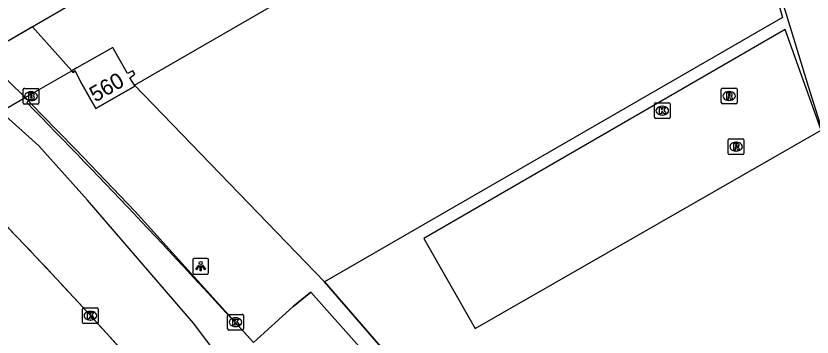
# Model space of a CAD drawing. Extents: x 155018 to 156648, y 383980 to 385733.
# Drawn here: x 155964.6 to 156015.3, y 385032.4 to 385052.9 of the extents above; entities that cross this region are included whole.
import ezdxf

# ---------------------------------------------------------------- set-up
doc = ezdxf.new("R2010")
doc.units = 0
for name, color, linetype in [('IMGEO_Brandkraan', 7, 'Continuous'), ('IMGEO_Dek', 7, 'Continuous'), ('IMGEO_Hek', 7, 'Continuous'), ('IMGEO_Kolk', 7, 'Continuous'), ('IMGEO_Lichtpunt', 7, 'Continuous'), ('IMGEO_OVBaan_gesloten', 7, 'Continuous'), ('IMGEO_Pand', 7, 'Continuous'), ('IMGEO_Pand_nummerreeks', 7, 'Continuous'), ('IMGEO_Pand_overbouw', 7, 'Continuous'), ('IMGEO_Parkeervlak_open', 7, 'Continuous'), ('IMGEO_Rijbaan_lokaal_gesloten', 7, 'Continuous'), ('IMGEO_Rijbaan_lokaal_open', 7, 'Continuous'), ('IMGEO_Rioolput', 7, 'Continuous'), ('IMGEO_Voetpad_gesloten', 7, 'Continuous'), ('IMGEO_Voetpad_open', 7, 'Continuous')]:
    doc.layers.add(name, color=color, linetype=linetype)

msp = doc.modelspace()

# ---------------------------------------------------------------- linework, layer by layer
at = {"layer": 'IMGEO_Brandkraan'}
for p, q in [((155965.097, 385047.34), (155965.097, 385048.192)), ((155965.172, 385048.266), (155966.024, 385048.266)), ((155966.098, 385048.192), (155966.098, 385047.34)), ((155965.585, 385048.046), (155965.61, 385048.046)), ((155966.024, 385047.266), (155965.172, 385047.266)), ((155965.608, 385047.486), (155965.583, 385047.486))]:
    msp.add_line(p, q, dxfattribs=at)
for points in [[(155965.097, 385047.34), (155965.097, 385048.192)], [(155965.172, 385048.266), (155966.024, 385048.266)], [(155966.098, 385048.192), (155966.098, 385047.34)], [(155965.445, 385047.966), (155965.445, 385047.566), (155965.658, 385047.566)], [(155965.676, 385047.966), (155965.445, 385047.966)], [(155965.624, 385047.885), (155965.57, 385047.885), (155965.57, 385047.809)], [(155965.57, 385047.809), (155965.623, 385047.809)], [(155965.632, 385047.733), (155965.57, 385047.733), (155965.57, 385047.652)], [(155965.57, 385047.652), (155965.632, 385047.652)], [(155966.024, 385047.266), (155965.172, 385047.266)]]:
    msp.add_lwpolyline(points, dxfattribs=at)
for centre, radius, start, end in [((155965.174, 385048.19), 0.0765, 91.552, 178.448), ((155965.174, 385048.19), 0.0765, 91.552, 178.448), ((155966.022, 385048.19), 0.0765, 1.552, 88.448), ((155966.022, 385048.19), 0.0765, 1.552, 88.448), ((155965.625, 385047.847), 0.0379, 267.8285, 90.9355), ((155965.633, 385047.692), 0.0404, 269.8759, 90.5077), ((155965.68, 385047.821), 0.145, 59.4692, 91.5367), ((155965.705, 385047.868), 0.0922, 285.5137, 58.1501), ((155965.71, 385047.676), 0.105, 301.3115, 78.989), ((155965.174, 385047.342), 0.0765, 181.552, 268.448), ((155965.174, 385047.342), 0.0765, 181.552, 268.448), ((155965.664, 385047.817), 0.251, 268.6676, 293.5347), ((155966.022, 385047.342), 0.0765, 271.552, 358.448), ((155966.022, 385047.342), 0.0765, 271.552, 358.448)]:
    msp.add_arc(centre, radius, start, end, dxfattribs=at)
for centre, major_axis, ratio, start_param, end_param in [((155965.584, 385047.766), (-0.387, 0.002), 0.722429, 4.712389, 7.853982), ((155965.609, 385047.766), (-0.39, 0.002), 0.717154, 1.570796, 4.712389)]:
    msp.add_ellipse(centre, major_axis=major_axis, ratio=ratio, start_param=start_param, end_param=end_param, dxfattribs=at)
at = {"layer": 'IMGEO_Dek'}
for points in [[(156017.88, 384995.994), (156015.235, 385000), (156010.18, 385006.034), (156009.47, 385006.881), (155984.292, 385035.94), (155972.197, 385048.471), (155972.178, 385048.46), (155972.215, 385048.398), (155969.718, 385046.978), (155968.762, 385048.658), (155968.405, 385049.379), (155968.276, 385049.284), (155968.2, 385049.386), (155965.699, 385052.187), (155964.931, 385051.744), (155962.573, 385050.383)], [(155963.734, 385039.816), (155965.63, 385037.827), (155967.511, 385035.822), (155969.375, 385033.803), (155971.223, 385031.769), (155973.056, 385029.721), (155974.872, 385027.658), (155972.373, 385025.357), (155980.461, 385016.334), (155993.065, 385002.273), (156005.259, 384985.766)]]:
    msp.add_lwpolyline(points, dxfattribs=at)
at = {"layer": 'IMGEO_Hek'}
for points in [[(155965.674, 385052.172), (155975.998, 385058.126)], [(156000, 385016.657), (155983.428, 385035.286)]]:
    msp.add_lwpolyline(points, dxfattribs=at)
at = {"layer": 'IMGEO_Kolk'}
for p, q in [((156005.306, 385046.42), (156005.306, 385047.272)), ((156005.381, 385047.346), (156006.233, 385047.346)), ((156006.307, 385047.272), (156006.307, 385046.42)), ((156005.794, 385047.126), (156005.819, 385047.126)), ((156006.233, 385046.346), (156005.381, 385046.346)), ((156005.817, 385046.566), (156005.792, 385046.566)), ((155968.878, 385033.361), (155968.878, 385034.213)), ((155968.953, 385034.287), (155969.805, 385034.287)), ((155969.366, 385034.067), (155969.391, 385034.067)), ((155969.879, 385034.213), (155969.879, 385033.361)), ((155969.389, 385033.507), (155969.364, 385033.507)), ((155978.121, 385032.95), (155978.121, 385033.802)), ((155978.196, 385033.876), (155979.048, 385033.876)), ((155978.609, 385033.656), (155978.634, 385033.656)), ((155979.122, 385033.802), (155979.122, 385032.95)), ((155969.805, 385033.287), (155968.953, 385033.287)), ((155978.632, 385033.096), (155978.607, 385033.096)), ((155979.048, 385032.876), (155978.196, 385032.876))]:
    msp.add_line(p, q, dxfattribs=at)
for points in [[(156005.306, 385046.42), (156005.306, 385047.272)], [(156005.381, 385047.346), (156006.233, 385047.346)], [(156006.307, 385047.272), (156006.307, 385046.42)], [(156005.627, 385047.046), (156005.75, 385047.046), (156005.75, 385046.895), (156005.88, 385047.046), (156006.044, 385047.046), (156005.898, 385046.895), (156006.051, 385046.646), (156005.899, 385046.646), (156005.814, 385046.81), (156005.75, 385046.743), (156005.75, 385046.646), (156005.627, 385046.646), (156005.627, 385047.046)], [(156006.233, 385046.346), (156005.381, 385046.346)], [(155968.878, 385033.361), (155968.878, 385034.213)], [(155968.953, 385034.287), (155969.805, 385034.287)], [(155969.199, 385033.987), (155969.322, 385033.987), (155969.322, 385033.836), (155969.452, 385033.987), (155969.616, 385033.987), (155969.47, 385033.836), (155969.623, 385033.587), (155969.471, 385033.587), (155969.386, 385033.751), (155969.322, 385033.684), (155969.322, 385033.587), (155969.199, 385033.587), (155969.199, 385033.987)], [(155969.879, 385034.213), (155969.879, 385033.361)], [(155978.121, 385032.95), (155978.121, 385033.802)], [(155978.196, 385033.876), (155979.048, 385033.876)], [(155978.442, 385033.576), (155978.565, 385033.576), (155978.565, 385033.425), (155978.695, 385033.576), (155978.859, 385033.576), (155978.713, 385033.425), (155978.866, 385033.176), (155978.714, 385033.176), (155978.629, 385033.34), (155978.565, 385033.273), (155978.565, 385033.176), (155978.442, 385033.176), (155978.442, 385033.576)], [(155979.122, 385033.802), (155979.122, 385032.95)], [(155969.805, 385033.287), (155968.953, 385033.287)], [(155979.048, 385032.876), (155978.196, 385032.876)]]:
    msp.add_lwpolyline(points, dxfattribs=at)
for centre, start, end in [((156005.383, 385047.27), 91.552, 178.448), ((156005.383, 385047.27), 91.552, 178.448), ((156006.231, 385047.27), 1.552, 88.448), ((156006.231, 385047.27), 1.552, 88.448), ((156005.383, 385046.422), 181.552, 268.448), ((156005.383, 385046.422), 181.552, 268.448), ((156006.231, 385046.422), 271.552, 358.448), ((156006.231, 385046.422), 271.552, 358.448), ((155968.955, 385034.211), 91.552, 178.448), ((155968.955, 385034.211), 91.552, 178.448), ((155969.803, 385034.211), 1.552, 88.448), ((155969.803, 385034.211), 1.552, 88.448), ((155978.198, 385033.8), 91.552, 178.448), ((155978.198, 385033.8), 91.552, 178.448), ((155979.046, 385033.8), 1.552, 88.448), ((155979.046, 385033.8), 1.552, 88.448), ((155968.955, 385033.363), 181.552, 268.448), ((155968.955, 385033.363), 181.552, 268.448), ((155969.803, 385033.363), 271.552, 358.448), ((155969.803, 385033.363), 271.552, 358.448), ((155978.198, 385032.952), 181.552, 268.448), ((155978.198, 385032.952), 181.552, 268.448), ((155979.046, 385032.952), 271.552, 358.448), ((155979.046, 385032.952), 271.552, 358.448)]:
    msp.add_arc(centre, 0.0765, start, end, dxfattribs=at)
for centre, major_axis, ratio, start_param, end_param in [((156005.793, 385046.846), (-0.387, 0.002), 0.722429, 4.712389, 7.853982), ((156005.818, 385046.846), (-0.39, 0.002), 0.717154, 1.570796, 4.712389), ((155969.365, 385033.787), (-0.387, 0.002), 0.722429, 4.712389, 7.853982), ((155969.39, 385033.787), (-0.39, 0.002), 0.717154, 1.570796, 4.712389), ((155978.608, 385033.376), (-0.387, 0.002), 0.722429, 4.712389, 7.853982), ((155978.633, 385033.376), (-0.39, 0.002), 0.717154, 1.570796, 4.712389)]:
    msp.add_ellipse(centre, major_axis=major_axis, ratio=ratio, start_param=start_param, end_param=end_param, dxfattribs=at)
at = {"layer": 'IMGEO_Lichtpunt'}
for p, q in [((155975.904, 385037.344), (155975.904, 385036.537)), ((155975.904, 385037.344), (155975.904, 385036.537)), ((155976.806, 385037.439), (155975.998, 385037.439)), ((155976.806, 385037.439), (155975.998, 385037.439)), ((155976.9, 385036.537), (155976.9, 385037.344)), ((155976.9, 385036.537), (155976.9, 385037.344)), ((155975.998, 385036.443), (155976.806, 385036.443)), ((155975.998, 385036.443), (155976.806, 385036.443))]:
    msp.add_line(p, q, dxfattribs=at)
for points in [[(155976.278, 385037.008), (155976.317, 385036.98), (155976.129, 385036.718), (155976.091, 385036.745), (155976.278, 385037.008)], [(155976.49, 385036.98), (155976.528, 385037.007), (155976.715, 385036.745), (155976.676, 385036.717), (155976.49, 385036.98)], [(155976.38, 385036.96), (155976.427, 385036.96), (155976.427, 385036.638), (155976.38, 385036.638), (155976.38, 385036.96)]]:
    msp.add_lwpolyline(points, dxfattribs=at)
msp.add_circle((155976.403, 385037.142), 0.0994, dxfattribs=at)
for centre, start, end in [((155975.998, 385037.344), 90, 180), ((155975.998, 385037.344), 90, 180), ((155976.806, 385037.344), 0, 90), ((155976.806, 385037.344), 0, 90), ((155975.998, 385036.537), 180, 270), ((155975.998, 385036.537), 180, 270), ((155976.806, 385036.537), 270, 0), ((155976.806, 385036.537), 270, 360)]:
    msp.add_arc(centre, 0.0946, start, end, dxfattribs=at)
at = {"layer": 'IMGEO_OVBaan_gesloten'}
for points in [[(155962.573, 385050.383), (155964.168, 385048.718), (155965.231, 385047.677), (155965.428, 385047.477), (155965.321, 385047.362)], [(155959.29, 385044.258), (155965.231, 385047.677)], [(155979.764, 385032.081), (155972.231, 385040.434), (155968.439, 385044.383), (155966.288, 385046.572), (155965.231, 385047.677)]]:
    msp.add_lwpolyline(points, dxfattribs=at)
for centre, radius, start, end in [((155569.91, 384659.169), 554.115, 42.29797, 44.47224), ((155712.784, 384798.739), 347.986, 41.1354, 43.85049), ((155712.784, 384798.739), 347.986, 41.1354, 43.85049)]:
    msp.add_arc(centre, radius, start, end, dxfattribs=at)
at = {"layer": 'IMGEO_Pand'}
for points in [[(155972.197, 385048.471), (156008.671, 385069.52)], [(156008.671, 385069.52), (156013.469, 385052.769), (155984.292, 385035.94)], [(155972.178, 385048.46), (155971.893, 385048.933), (155972.201, 385049.166), (155972.089, 385049.388), (155971.735, 385049.212), (155970.85, 385050.779), (155970.797, 385050.871), (155968.52, 385049.57), (155968.2, 385049.386)], [(155968.2, 385049.386), (155968.276, 385049.284), (155968.405, 385049.379), (155968.762, 385048.658), (155969.718, 385046.978), (155972.215, 385048.398), (155972.178, 385048.46)], [(155972.197, 385048.471), (155984.292, 385035.94)]]:
    msp.add_lwpolyline(points, dxfattribs=at)
at = {"layer": 'IMGEO_Pand_overbouw'}
msp.add_lwpolyline([(156037.638, 384939.699), (156032.938, 384949.258), (156031.228, 384952.424), (156028.885, 384956.762), (156023.824, 384965.729), (156015.329, 384979.293), (156010.047, 384987.197), (156004.748, 384994.572), (156003.959, 384995.67), (155994.678, 385008.257), (155982.028, 385025.261), (155975.946, 385033.308), (155969.19, 385041.146), (155966.094, 385044.608), (155960.986, 385049.184), (155953.94, 385055.371)], dxfattribs=at)
at = {"layer": 'IMGEO_Parkeervlak_open'}
msp.add_lwpolyline([(156029.136, 384994.099), (156032.711, 384996.172), (156033.064, 384996.374), (156024.751, 385019.02), (156019.719, 385033.828), (156015.201, 385048.103), (156012.694, 385056.311), (156008.803, 385069.59)], dxfattribs=at)
at = {"layer": 'IMGEO_Rijbaan_lokaal_gesloten'}
msp.add_lwpolyline([(156015.926, 385045.612), (156013.645, 385052.003), (155990.628, 385038.7), (155993.886, 385032.966), (156015.926, 385045.612)], dxfattribs=at)
at = {"layer": 'IMGEO_Rijbaan_lokaal_open'}
for points in [[(155968.6, 385053.859), (155962.573, 385050.383)], [(155965.231, 385047.677), (155968.2, 385049.386)], [(155972.178, 385048.46), (155972.197, 385048.471)]]:
    msp.add_lwpolyline(points, dxfattribs=at)
at = {"layer": 'IMGEO_Rioolput'}
for p, q in [((156009.567, 385047.354), (156009.567, 385048.206)), ((156009.642, 385048.28), (156010.494, 385048.28)), ((156010.568, 385048.206), (156010.568, 385047.354)), ((156010.055, 385048.06), (156010.08, 385048.06)), ((156010.494, 385047.28), (156009.642, 385047.28)), ((156010.078, 385047.5), (156010.053, 385047.5)), ((156010.008, 385044.125), (156010.008, 385044.977)), ((156010.083, 385045.051), (156010.935, 385045.051)), ((156010.496, 385044.831), (156010.521, 385044.831)), ((156011.009, 385044.977), (156011.009, 385044.125)), ((156010.519, 385044.271), (156010.494, 385044.271)), ((156010.935, 385044.051), (156010.083, 385044.051))]:
    msp.add_line(p, q, dxfattribs=at)
for points in [[(156009.567, 385047.354), (156009.567, 385048.206)], [(156009.642, 385048.28), (156010.494, 385048.28)], [(156010.568, 385048.206), (156010.568, 385047.354)], [(156010.156, 385047.978), (156009.904, 385047.98), (156009.904, 385047.58)], [(156009.904, 385047.58), (156010.028, 385047.58), (156010.028, 385047.742), (156010.039, 385047.742)], [(156010.082, 385047.899), (156010.028, 385047.899), (156010.028, 385047.818)], [(156010.028, 385047.818), (156010.08, 385047.818)], [(156010.086, 385047.713), (156010.157, 385047.58), (156010.297, 385047.58), (156010.232, 385047.706)], [(156010.494, 385047.28), (156009.642, 385047.28)], [(156010.008, 385044.125), (156010.008, 385044.977)], [(156010.083, 385045.051), (156010.935, 385045.051)], [(156010.597, 385044.749), (156010.345, 385044.751), (156010.345, 385044.351)], [(156010.523, 385044.67), (156010.469, 385044.67), (156010.469, 385044.589)], [(156011.009, 385044.977), (156011.009, 385044.125)], [(156010.345, 385044.351), (156010.469, 385044.351), (156010.469, 385044.513), (156010.48, 385044.513)], [(156010.469, 385044.589), (156010.521, 385044.589)], [(156010.527, 385044.484), (156010.598, 385044.351), (156010.738, 385044.351), (156010.673, 385044.477)], [(156010.935, 385044.051), (156010.083, 385044.051)]]:
    msp.add_lwpolyline(points, dxfattribs=at)
for centre, radius, start, end in [((156009.644, 385048.204), 0.0765, 91.552, 178.448), ((156009.644, 385048.204), 0.0765, 91.552, 178.448), ((156010.492, 385048.204), 0.0765, 1.552, 88.448), ((156010.492, 385048.204), 0.0765, 1.552, 88.448), ((156010.038, 385047.689), 0.0533, 26.0293, 88.6989), ((156010.064, 385048.007), 0.19, 274.7715, 282.9687), ((156010.088, 385047.803), 0.0964, 77.0061, 93.1865), ((156010.102, 385047.86), 0.0378, 276.6634, 79.6772), ((156010.155, 385047.868), 0.109, 350.3612, 89.416), ((156010.153, 385047.868), 0.112, 277.5842, 350.9817), ((156010.137, 385047.653), 0.108, 29.5134, 73.7905), ((156009.644, 385047.356), 0.0765, 181.552, 268.448), ((156009.644, 385047.356), 0.0765, 181.552, 268.448), ((156010.492, 385047.356), 0.0765, 271.552, 358.448), ((156010.492, 385047.356), 0.0765, 271.552, 358.448), ((156010.085, 385044.975), 0.0765, 91.552, 178.448), ((156010.085, 385044.975), 0.0765, 91.552, 178.448), ((156010.529, 385044.574), 0.0964, 77.0061, 93.1865), ((156010.543, 385044.631), 0.0378, 276.6634, 79.6772), ((156010.596, 385044.639), 0.109, 350.3612, 89.416), ((156010.594, 385044.639), 0.112, 277.5842, 350.9817), ((156010.933, 385044.975), 0.0765, 1.552, 88.448), ((156010.933, 385044.975), 0.0765, 1.552, 88.448), ((156010.085, 385044.127), 0.0765, 181.552, 268.448), ((156010.085, 385044.127), 0.0765, 181.552, 268.448), ((156010.479, 385044.46), 0.0533, 26.0293, 88.6989), ((156010.505, 385044.778), 0.19, 274.7715, 282.9687), ((156010.578, 385044.424), 0.108, 29.5134, 73.7905), ((156010.933, 385044.127), 0.0765, 271.552, 358.448), ((156010.933, 385044.127), 0.0765, 271.552, 358.448)]:
    msp.add_arc(centre, radius, start, end, dxfattribs=at)
for centre, major_axis, ratio, start_param, end_param in [((156010.054, 385047.78), (-0.387, 0.002), 0.722429, 4.712389, 7.853982), ((156010.079, 385047.78), (-0.39, 0.002), 0.717154, 1.570796, 4.712389), ((156010.495, 385044.551), (-0.387, 0.002), 0.722429, 4.712389, 7.853982), ((156010.52, 385044.551), (-0.39, 0.002), 0.717154, 1.570796, 4.712389)]:
    msp.add_ellipse(centre, major_axis=major_axis, ratio=ratio, start_param=start_param, end_param=end_param, dxfattribs=at)
at = {"layer": 'IMGEO_Voetpad_gesloten'}
for points in [[(156017.88, 384995.994), (156015.235, 385000), (156010.18, 385006.034), (156009.47, 385006.881), (155984.292, 385035.94), (155972.197, 385048.471), (155972.178, 385048.46), (155972.215, 385048.398), (155969.718, 385046.978), (155968.762, 385048.658), (155968.405, 385049.379), (155968.276, 385049.284), (155968.2, 385049.386), (155965.699, 385052.187), (155964.931, 385051.744), (155962.573, 385050.383)], [(155979.764, 385032.081), (155982.297, 385034.384), (155983.428, 385035.286), (156000, 385016.657), (156004.098, 385012.193), (156000.456, 385008.847)]]:
    msp.add_lwpolyline(points, dxfattribs=at)
at = {"layer": 'IMGEO_Voetpad_open'}
for points in [[(155984.292, 385035.94), (156009.47, 385006.881)], [(156004.098, 385012.193), (156000, 385016.657), (155983.428, 385035.286), (155982.297, 385034.384), (155979.764, 385032.081)]]:
    msp.add_lwpolyline(points, dxfattribs=at)

# ---------------------------------------------------------------- texts
at = {"layer": 'IMGEO_Pand_nummerreeks'}
msp.add_text('560', height=1, rotation=29.7422, dxfattribs=at).set_placement((155969.687, 385047.357))

doc.saveas('drawing.dxf')
